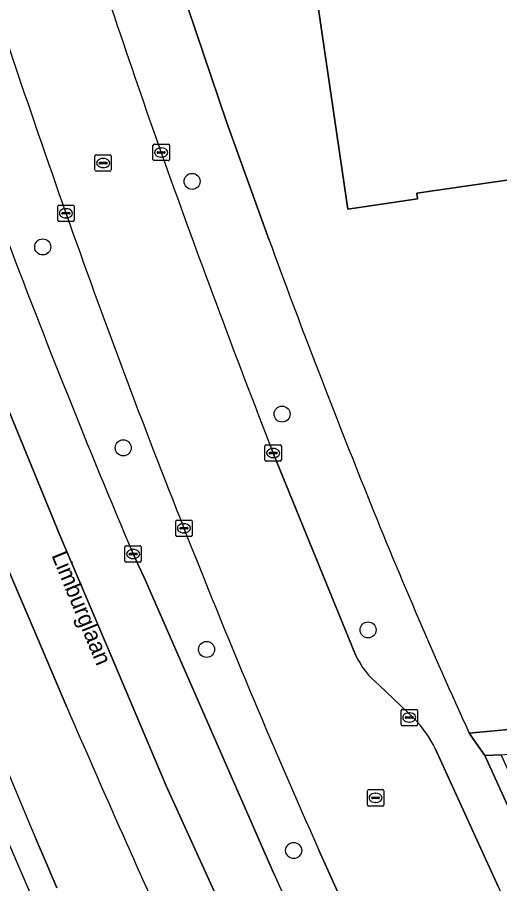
# Model space of a CAD drawing. Extents: x 159499 to 160349, y 382524 to 383273.
# Drawn here: x 159624.2 to 159653.7, y 382615.1 to 382668 of the extents above; entities that cross this region are included whole.
import ezdxf

# ---------------------------------------------------------------- set-up
doc = ezdxf.new("R2010")
doc.units = 0
for name, color, linetype in [('IMGEO_Berm_groen', 7, 'Continuous'), ('IMGEO_Boom', 7, 'Continuous'), ('IMGEO_Erf', 7, 'Continuous'), ('IMGEO_Kolk', 7, 'Continuous'), ('IMGEO_Openbare_ruimte_label', 7, 'Continuous'), ('IMGEO_Pand', 7, 'Continuous'), ('IMGEO_Rijbaan_lokaal_open', 7, 'Continuous'), ('IMGEO_Rijbaan_regionaal_gesloten', 7, 'Continuous'), ('IMGEO_Rioolput', 7, 'Continuous'), ('IMGEO_Voetpad_open', 7, 'Continuous')]:
    doc.layers.add(name, color=color, linetype=linetype)

msp = doc.modelspace()

# ---------------------------------------------------------------- linework, layer by layer
at = {"layer": 'IMGEO_Berm_groen'}
for points in [[(159627.268, 382625.892), (159625.439, 382630.208), (159622.906, 382636.08)], [(159631.301, 382635.251), (159631.64, 382634.537), (159631.979, 382633.823), (159639.351, 382616.939), (159639.855, 382615.784)], [(159625.399, 382617.813), (159626.021, 382616.345), (159626.646, 382614.878)], [(159656.974, 382586.721), (159656.453, 382588.103), (159652.943, 382595.197), (159650.016, 382601.179), (159647.894, 382605.529), (159647.401, 382606.58), (159642.633, 382617.174)]]:
    msp.add_lwpolyline(points, dxfattribs=at)
for centre, radius, start, end in [((160288.417, 382888.96), 701.029, 197.7259, 199.40505), ((160128.258, 382832.54), 531.223, 199.4047, 201.6192), ((160145.033, 382852.048), 557.603, 200.70173, 202.88), ((160233.383, 382874.286), 659.866, 200.680212, 202.872025), ((160085.442, 382814.192), 484.661, 201.46766, 203.98563), ((160306.476, 382918.298), 739.476, 203.292387, 203.993908), ((160293.165, 382912.408), 724.92, 203.99639, 204.86476), ((159974.799, 382766.166), 367.154, 204.17893, 207.66337)]:
    msp.add_arc(centre, radius, start, end, dxfattribs=at)
at = {"layer": 'IMGEO_Boom'}
for centre in [(159634.899, 382657.996), (159625.793, 382653.99), (159640.39, 382643.791), (159630.703, 382641.728), (159645.632, 382630.613), (159635.784, 382629.422), (159641.094, 382617.148)]:
    msp.add_circle(centre, 0.489, dxfattribs=at)
at = {"layer": 'IMGEO_Erf'}
for points in [[(159656.75, 382658.455), (159648.598, 382657.265), (159648.647, 382656.927), (159644.395, 382656.307), (159642.066, 382672.269), (159643.442, 382672.47), (159641.857, 382683.335), (159640.997, 382683.21), (159638.66, 382701.423)], [(159627.166, 382691.73), (159633.264, 382672.724), (159636.993, 382661.627), (159639.603, 382654.41)], [(159651.799, 382624.316), (159655.72, 382624.685), (159679.397, 382627.147), (159681.206, 382628.947)]]:
    msp.add_lwpolyline(points, dxfattribs=at)
for centre, radius, start, end in [((160108.471, 382825.391), 499.071, 200.03529, 201.89663), ((159957.714, 382763.975), 336.287, 201.76661, 204.53806)]:
    msp.add_arc(centre, radius, start, end, dxfattribs=at)
at = {"layer": 'IMGEO_Kolk'}
for p, q in [((159632.516, 382659.333), (159632.516, 382660.185)), ((159632.591, 382660.259), (159633.443, 382660.259)), ((159633.517, 382660.185), (159633.517, 382659.333)), ((159632.775, 382659.753), (159632.775, 382659.765)), ((159633.213, 382659.716), (159632.815, 382659.716)), ((159632.818, 382659.802), (159633.216, 382659.802)), ((159633.004, 382660.039), (159633.029, 382660.039)), ((159633.259, 382659.765), (159633.259, 382659.753)), ((159633.443, 382659.259), (159632.591, 382659.259)), ((159633.027, 382659.479), (159633.002, 382659.479)), ((159626.709, 382655.621), (159626.709, 382656.473)), ((159626.784, 382656.547), (159627.636, 382656.547)), ((159627.71, 382656.473), (159627.71, 382655.621)), ((159626.968, 382656.041), (159626.968, 382656.053)), ((159627.406, 382656.004), (159627.008, 382656.004)), ((159627.011, 382656.09), (159627.409, 382656.09)), ((159627.197, 382656.327), (159627.222, 382656.327)), ((159627.452, 382656.053), (159627.452, 382656.041)), ((159627.636, 382655.547), (159626.784, 382655.547)), ((159627.22, 382655.767), (159627.195, 382655.767)), ((159639.342, 382640.986), (159639.342, 382641.838)), ((159639.417, 382641.912), (159640.269, 382641.912)), ((159639.83, 382641.692), (159639.855, 382641.692)), ((159640.343, 382641.838), (159640.343, 382640.986)), ((159639.601, 382641.406), (159639.601, 382641.418)), ((159640.039, 382641.369), (159639.641, 382641.369)), ((159639.644, 382641.455), (159640.042, 382641.455)), ((159639.853, 382641.132), (159639.828, 382641.132)), ((159640.085, 382641.418), (159640.085, 382641.406)), ((159640.269, 382640.912), (159639.417, 382640.912)), ((159633.903, 382636.391), (159633.903, 382637.243)), ((159633.978, 382637.317), (159634.83, 382637.317)), ((159634.391, 382637.097), (159634.416, 382637.097)), ((159634.904, 382637.243), (159634.904, 382636.391)), ((159634.162, 382636.811), (159634.162, 382636.823)), ((159634.6, 382636.774), (159634.202, 382636.774)), ((159634.205, 382636.86), (159634.603, 382636.86)), ((159634.414, 382636.537), (159634.389, 382636.537)), ((159634.646, 382636.823), (159634.646, 382636.811)), ((159634.83, 382636.317), (159633.978, 382636.317)), ((159630.803, 382634.822), (159630.803, 382635.674)), ((159630.878, 382635.748), (159631.73, 382635.748)), ((159631.291, 382635.528), (159631.316, 382635.528)), ((159631.804, 382635.674), (159631.804, 382634.822)), ((159631.062, 382635.242), (159631.062, 382635.254)), ((159631.5, 382635.205), (159631.102, 382635.205)), ((159631.105, 382635.291), (159631.503, 382635.291)), ((159631.314, 382634.968), (159631.289, 382634.968)), ((159631.546, 382635.254), (159631.546, 382635.242)), ((159631.73, 382634.748), (159630.878, 382634.748)), ((159647.643, 382624.838), (159647.643, 382625.69)), ((159647.718, 382625.764), (159648.57, 382625.764)), ((159647.902, 382625.258), (159647.902, 382625.27)), ((159647.945, 382625.307), (159648.343, 382625.307)), ((159648.131, 382625.544), (159648.156, 382625.544)), ((159648.386, 382625.27), (159648.386, 382625.258)), ((159648.644, 382625.69), (159648.644, 382624.838)), ((159648.57, 382624.764), (159647.718, 382624.764)), ((159648.34, 382625.221), (159647.942, 382625.221)), ((159648.154, 382624.984), (159648.129, 382624.984))]:
    msp.add_line(p, q, dxfattribs=at)
for points in [[(159632.516, 382659.333), (159632.516, 382660.185)], [(159632.591, 382660.259), (159633.443, 382660.259)], [(159633.517, 382660.185), (159633.517, 382659.333)], [(159633.443, 382659.259), (159632.591, 382659.259)], [(159626.709, 382655.621), (159626.709, 382656.473)], [(159626.784, 382656.547), (159627.636, 382656.547)], [(159627.71, 382656.473), (159627.71, 382655.621)], [(159627.636, 382655.547), (159626.784, 382655.547)], [(159639.342, 382640.986), (159639.342, 382641.838)], [(159639.417, 382641.912), (159640.269, 382641.912)], [(159640.343, 382641.838), (159640.343, 382640.986)], [(159640.269, 382640.912), (159639.417, 382640.912)], [(159633.903, 382636.391), (159633.903, 382637.243)], [(159633.978, 382637.317), (159634.83, 382637.317)], [(159634.904, 382637.243), (159634.904, 382636.391)], [(159634.83, 382636.317), (159633.978, 382636.317)], [(159630.803, 382634.822), (159630.803, 382635.674)], [(159630.878, 382635.748), (159631.73, 382635.748)], [(159631.804, 382635.674), (159631.804, 382634.822)], [(159631.73, 382634.748), (159630.878, 382634.748)], [(159647.643, 382624.838), (159647.643, 382625.69)], [(159647.718, 382625.764), (159648.57, 382625.764)], [(159648.644, 382625.69), (159648.644, 382624.838)], [(159648.57, 382624.764), (159647.718, 382624.764)]]:
    msp.add_lwpolyline(points, dxfattribs=at)
for centre, radius, start, end in [((159632.593, 382660.183), 0.0765, 91.552, 178.448), ((159632.593, 382660.183), 0.0765, 91.552, 178.448), ((159633.441, 382660.183), 0.0765, 1.552, 88.448), ((159633.441, 382660.183), 0.0765, 1.552, 88.448), ((159632.815, 382659.762), 0.0403, 85.8775, 175.7526), ((159632.812, 382659.752), 0.0366, 178.938, 274.7102), ((159633.216, 382659.759), 0.043, 264.8664, 352.4533), ((159633.22, 382659.764), 0.0386, 1.7309, 96.639), ((159632.593, 382659.335), 0.0765, 181.552, 268.448), ((159632.593, 382659.335), 0.0765, 181.552, 268.448), ((159633.441, 382659.335), 0.0765, 271.552, 358.448), ((159633.441, 382659.335), 0.0765, 271.552, 358.448), ((159626.786, 382656.471), 0.0765, 91.552, 178.448), ((159626.786, 382656.471), 0.0765, 91.552, 178.448), ((159627.634, 382656.471), 0.0765, 1.552, 88.448), ((159627.634, 382656.471), 0.0765, 1.552, 88.448), ((159627.008, 382656.05), 0.0403, 85.8775, 175.7526), ((159627.005, 382656.04), 0.0366, 178.938, 274.7102), ((159627.409, 382656.047), 0.043, 264.8664, 352.4533), ((159627.413, 382656.052), 0.0386, 1.7309, 96.639), ((159626.786, 382655.623), 0.0765, 181.552, 268.448), ((159626.786, 382655.623), 0.0765, 181.552, 268.448), ((159627.634, 382655.623), 0.0765, 271.552, 358.448), ((159627.634, 382655.623), 0.0765, 271.552, 358.448), ((159639.419, 382641.836), 0.0765, 91.552, 178.448), ((159639.419, 382641.836), 0.0765, 91.552, 178.448), ((159640.267, 382641.836), 0.0765, 1.552, 88.448), ((159640.267, 382641.836), 0.0765, 1.552, 88.448), ((159639.641, 382641.415), 0.0403, 85.8775, 175.7526), ((159639.638, 382641.405), 0.0366, 178.938, 274.7102), ((159640.042, 382641.412), 0.043, 264.8664, 352.4533), ((159640.046, 382641.417), 0.0386, 1.7309, 96.639), ((159639.419, 382640.988), 0.0765, 181.552, 268.448), ((159639.419, 382640.988), 0.0765, 181.552, 268.448), ((159640.267, 382640.988), 0.0765, 271.552, 358.448), ((159640.267, 382640.988), 0.0765, 271.552, 358.448), ((159633.98, 382637.241), 0.0765, 91.552, 178.448), ((159633.98, 382637.241), 0.0765, 91.552, 178.448), ((159634.828, 382637.241), 0.0765, 1.552, 88.448), ((159634.828, 382637.241), 0.0765, 1.552, 88.448), ((159633.98, 382636.393), 0.0765, 181.552, 268.448), ((159633.98, 382636.393), 0.0765, 181.552, 268.448), ((159634.202, 382636.82), 0.0403, 85.8775, 175.7526), ((159634.199, 382636.81), 0.0366, 178.938, 274.7102), ((159634.603, 382636.817), 0.043, 264.8664, 352.4533), ((159634.607, 382636.822), 0.0386, 1.7309, 96.639), ((159634.828, 382636.393), 0.0765, 271.552, 358.448), ((159634.828, 382636.393), 0.0765, 271.552, 358.448), ((159630.88, 382635.672), 0.0765, 91.552, 178.448), ((159630.88, 382635.672), 0.0765, 91.552, 178.448), ((159631.728, 382635.672), 0.0765, 1.552, 88.448), ((159631.728, 382635.672), 0.0765, 1.552, 88.448), ((159630.88, 382634.824), 0.0765, 181.552, 268.448), ((159630.88, 382634.824), 0.0765, 181.552, 268.448), ((159631.102, 382635.251), 0.0403, 85.8775, 175.7526), ((159631.099, 382635.241), 0.0366, 178.938, 274.7102), ((159631.503, 382635.248), 0.043, 264.8664, 352.4533), ((159631.507, 382635.253), 0.0386, 1.7309, 96.639), ((159631.728, 382634.824), 0.0765, 271.552, 358.448), ((159631.728, 382634.824), 0.0765, 271.552, 358.448), ((159647.72, 382625.688), 0.0765, 91.552, 178.448), ((159647.72, 382625.688), 0.0765, 91.552, 178.448), ((159647.942, 382625.267), 0.0403, 85.8775, 175.7526), ((159647.939, 382625.257), 0.0366, 178.938, 274.7102), ((159648.343, 382625.264), 0.043, 264.8664, 352.4533), ((159648.347, 382625.269), 0.0386, 1.7309, 96.639), ((159648.568, 382625.688), 0.0765, 1.552, 88.448), ((159648.568, 382625.688), 0.0765, 1.552, 88.448), ((159647.72, 382624.84), 0.0765, 181.552, 268.448), ((159647.72, 382624.84), 0.0765, 181.552, 268.448), ((159648.568, 382624.84), 0.0765, 271.552, 358.448), ((159648.568, 382624.84), 0.0765, 271.552, 358.448)]:
    msp.add_arc(centre, radius, start, end, dxfattribs=at)
for centre, major_axis, ratio, start_param, end_param in [((159633.003, 382659.759), (-0.387, 0.002), 0.722429, 4.712389, 7.853982), ((159633.028, 382659.759), (-0.39, 0.002), 0.717154, 1.570796, 4.712389), ((159627.196, 382656.047), (-0.387, 0.002), 0.722429, 4.712389, 7.853982), ((159627.221, 382656.047), (-0.39, 0.002), 0.717154, 1.570796, 4.712389), ((159639.829, 382641.412), (-0.387, 0.002), 0.722429, 4.712389, 7.853982), ((159639.854, 382641.412), (-0.39, 0.002), 0.717154, 1.570796, 4.712389), ((159634.39, 382636.817), (-0.387, 0.002), 0.722429, 4.712389, 7.853982), ((159634.415, 382636.817), (-0.39, 0.002), 0.717154, 1.570796, 4.712389), ((159631.29, 382635.248), (-0.387, 0.002), 0.722429, 4.712389, 7.853982), ((159631.315, 382635.248), (-0.39, 0.002), 0.717154, 1.570796, 4.712389), ((159648.13, 382625.264), (-0.387, 0.002), 0.722429, 4.712389, 7.853982), ((159648.155, 382625.264), (-0.39, 0.002), 0.717154, 1.570796, 4.712389)]:
    msp.add_ellipse(centre, major_axis=major_axis, ratio=ratio, start_param=start_param, end_param=end_param, dxfattribs=at)
at = {"layer": 'IMGEO_Pand'}
msp.add_lwpolyline([(159638.66, 382701.423), (159640.997, 382683.21), (159641.857, 382683.335), (159643.442, 382672.47), (159642.066, 382672.269), (159644.395, 382656.307), (159648.647, 382656.927), (159648.598, 382657.265), (159656.75, 382658.455), (159659.453, 382639.936), (159656.427, 382639.494), (159657.299, 382633.515), (159674.654, 382636.047), (159673.787, 382641.988), (159670.783, 382641.55), (159667.4, 382664.726), (159676.502, 382666.054), (159683.769, 382667.115), (159683.967, 382665.716), (159686.027, 382651.138)], dxfattribs=at)
at = {"layer": 'IMGEO_Rijbaan_lokaal_open'}
for points in [[(159644.858, 382629.099), (159639.842, 382641.412)], [(159648.463, 382625.194), (159646.308, 382627.242)], [(159653.555, 382614.944), (159649.718, 382623.375)], [(159656.147, 382617.762), (159653.754, 382622.997), (159652.76, 382622.944), (159655.372, 382617.19)], [(159642.633, 382617.174), (159647.401, 382606.58), (159647.894, 382605.529), (159652.183, 382607.459), (159651.95, 382608), (159651.88, 382608.3)]]:
    msp.add_lwpolyline(points, dxfattribs=at)
for centre, radius, start, end in [((160063.968, 382812.706), 457.288, 197.34631, 199.54014), ((160288.417, 382888.96), 701.029, 197.7259, 199.40505), ((160237.548, 382874.244), 641.454, 199.534476, 201.282993), ((160128.258, 382832.54), 531.223, 199.4047, 201.6192), ((160085.442, 382814.192), 484.661, 201.46766, 203.98563), ((159649.602, 382631.308), 5.233, 204.9739, 230.9936), ((159642.994, 382620.078), 7.489, 26.1184, 43.0882)]:
    msp.add_arc(centre, radius, start, end, dxfattribs=at)
at = {"layer": 'IMGEO_Rijbaan_regionaal_gesloten'}
for points in [[(159520.329, 382931.656), (159615.056, 382637.733), (159624.264, 382616.336), (159640.088, 382579.566), (159669.759, 382530.382)], [(159664.433, 382555.041), (159677.399, 382534.95), (159680.3, 382536.685), (159675.749, 382543.769), (159671.381, 382550.566), (159667.195, 382557.349), (159663.03, 382564.222), (159658.988, 382571.17), (159654.991, 382578.106), (159651.187, 382585.048), (159647.329, 382592.243), (159643.665, 382599.386), (159640.072, 382606.566), (159636.648, 382613.773), (159633.328, 382621.089), (159630.021, 382628.89), (159626.836, 382636.403), (159623.747, 382643.956)], [(159623.747, 382643.956), (159626.836, 382636.403), (159630.021, 382628.89), (159633.328, 382621.089), (159636.648, 382613.773), (159640.072, 382606.566), (159643.665, 382599.386), (159647.329, 382592.243), (159651.187, 382585.048), (159654.991, 382578.106), (159658.988, 382571.17), (159663.03, 382564.222), (159667.195, 382557.349), (159671.381, 382550.566), (159675.749, 382543.769), (159680.3, 382536.685), (159683.313, 382538.487), (159677.371, 382547.652), (159670.759, 382558.203)], [(159622.906, 382636.08), (159625.439, 382630.208), (159627.268, 382625.892)], [(159639.855, 382615.784), (159639.351, 382616.939), (159631.979, 382633.823), (159631.64, 382634.537), (159631.301, 382635.251)], [(159626.646, 382614.878), (159626.021, 382616.345), (159625.399, 382617.813)]]:
    msp.add_lwpolyline(points, dxfattribs=at)
for centre, radius, start, end in [((160145.033, 382852.048), 557.603, 200.70173, 202.88), ((160233.383, 382874.286), 659.866, 200.680212, 202.872025), ((160306.476, 382918.298), 739.476, 203.292387, 203.993908), ((160293.165, 382912.408), 724.92, 203.99639, 204.86476), ((159974.799, 382766.166), 367.154, 204.17893, 207.66337)]:
    msp.add_arc(centre, radius, start, end, dxfattribs=at)
at = {"layer": 'IMGEO_Rioolput'}
for p, q in [((159628.975, 382658.689), (159628.975, 382659.541)), ((159629.05, 382659.615), (159629.902, 382659.615)), ((159629.234, 382659.109), (159629.234, 382659.121)), ((159629.277, 382659.158), (159629.675, 382659.158)), ((159629.463, 382659.395), (159629.488, 382659.395)), ((159629.718, 382659.121), (159629.718, 382659.109)), ((159629.976, 382659.541), (159629.976, 382658.689)), ((159629.902, 382658.615), (159629.05, 382658.615)), ((159629.672, 382659.072), (159629.274, 382659.072)), ((159629.486, 382658.835), (159629.461, 382658.835)), ((159645.589, 382619.936), (159645.589, 382620.788)), ((159645.664, 382620.862), (159646.516, 382620.862)), ((159646.077, 382620.642), (159646.102, 382620.642)), ((159646.59, 382620.788), (159646.59, 382619.936)), ((159645.848, 382620.356), (159645.848, 382620.368)), ((159646.286, 382620.319), (159645.888, 382620.319)), ((159645.891, 382620.405), (159646.289, 382620.405)), ((159646.1, 382620.082), (159646.075, 382620.082)), ((159646.332, 382620.368), (159646.332, 382620.356)), ((159646.516, 382619.862), (159645.664, 382619.862))]:
    msp.add_line(p, q, dxfattribs=at)
for points in [[(159628.975, 382658.689), (159628.975, 382659.541)], [(159629.05, 382659.615), (159629.902, 382659.615)], [(159629.976, 382659.541), (159629.976, 382658.689)], [(159629.902, 382658.615), (159629.05, 382658.615)], [(159645.589, 382619.936), (159645.589, 382620.788)], [(159645.664, 382620.862), (159646.516, 382620.862)], [(159646.59, 382620.788), (159646.59, 382619.936)], [(159646.516, 382619.862), (159645.664, 382619.862)]]:
    msp.add_lwpolyline(points, dxfattribs=at)
for centre, radius, start, end in [((159629.052, 382659.539), 0.0765, 91.552, 178.448), ((159629.052, 382659.539), 0.0765, 91.552, 178.448), ((159629.274, 382659.118), 0.0403, 85.8775, 175.7526), ((159629.271, 382659.108), 0.0366, 178.938, 274.7102), ((159629.675, 382659.115), 0.043, 264.8664, 352.4533), ((159629.679, 382659.12), 0.0386, 1.7309, 96.639), ((159629.9, 382659.539), 0.0765, 1.552, 88.448), ((159629.9, 382659.539), 0.0765, 1.552, 88.448), ((159629.052, 382658.691), 0.0765, 181.552, 268.448), ((159629.052, 382658.691), 0.0765, 181.552, 268.448), ((159629.9, 382658.691), 0.0765, 271.552, 358.448), ((159629.9, 382658.691), 0.0765, 271.552, 358.448), ((159645.666, 382620.786), 0.0765, 91.552, 178.448), ((159645.666, 382620.786), 0.0765, 91.552, 178.448), ((159646.514, 382620.786), 0.0765, 1.552, 88.448), ((159646.514, 382620.786), 0.0765, 1.552, 88.448), ((159645.888, 382620.365), 0.0403, 85.8775, 175.7526), ((159645.885, 382620.355), 0.0366, 178.938, 274.7102), ((159646.289, 382620.362), 0.043, 264.8664, 352.4533), ((159646.293, 382620.367), 0.0386, 1.7309, 96.639), ((159645.666, 382619.938), 0.0765, 181.552, 268.448), ((159645.666, 382619.938), 0.0765, 181.552, 268.448), ((159646.514, 382619.938), 0.0765, 271.552, 358.448), ((159646.514, 382619.938), 0.0765, 271.552, 358.448)]:
    msp.add_arc(centre, radius, start, end, dxfattribs=at)
for centre, major_axis, ratio, start_param, end_param in [((159629.462, 382659.115), (-0.387, 0.002), 0.722429, 4.712389, 7.853982), ((159629.487, 382659.115), (-0.39, 0.002), 0.717154, 1.570796, 4.712389), ((159646.076, 382620.362), (-0.387, 0.002), 0.722429, 4.712389, 7.853982), ((159646.101, 382620.362), (-0.39, 0.002), 0.717154, 1.570796, 4.712389)]:
    msp.add_ellipse(centre, major_axis=major_axis, ratio=ratio, start_param=start_param, end_param=end_param, dxfattribs=at)
at = {"layer": 'IMGEO_Voetpad_open'}
for points in [[(159639.603, 382654.41), (159636.993, 382661.627), (159633.264, 382672.724), (159627.166, 382691.73)], [(159639.842, 382641.412), (159644.858, 382629.099)], [(159646.308, 382627.242), (159648.463, 382625.194)], [(159678.741, 382626.446), (159679.397, 382627.147), (159655.72, 382624.685), (159651.799, 382624.316), (159652.76, 382622.944), (159653.754, 382622.997), (159658.352, 382623.413), (159664.14, 382623.954), (159676.278, 382625.327)], [(159666.118, 382593.788), (159660.451, 382605.328), (159655.373, 382615.968), (159655.372, 382617.19), (159652.76, 382622.944), (159651.799, 382624.316)], [(159649.718, 382623.375), (159653.555, 382614.944), (159655.211, 382611.278), (159659.907, 382600.998), (159663.773, 382592.582)]]:
    msp.add_lwpolyline(points, dxfattribs=at)
for centre, radius, start, end in [((160063.968, 382812.706), 457.288, 197.34631, 199.54014), ((160237.548, 382874.244), 641.454, 199.534476, 201.282993), ((160108.471, 382825.391), 499.071, 200.03529, 201.89663), ((159957.714, 382763.975), 336.287, 201.76661, 204.53806), ((159649.602, 382631.308), 5.233, 204.9739, 230.9936), ((159642.994, 382620.078), 7.489, 26.1184, 43.0882)]:
    msp.add_arc(centre, radius, start, end, dxfattribs=at)

# ---------------------------------------------------------------- texts
at = {"layer": 'IMGEO_Openbare_ruimte_label'}
msp.add_text('Limburglaan', height=1, rotation=292.3334, dxfattribs=at).set_placement((159626.309, 382635.169))

doc.saveas('drawing.dxf')
